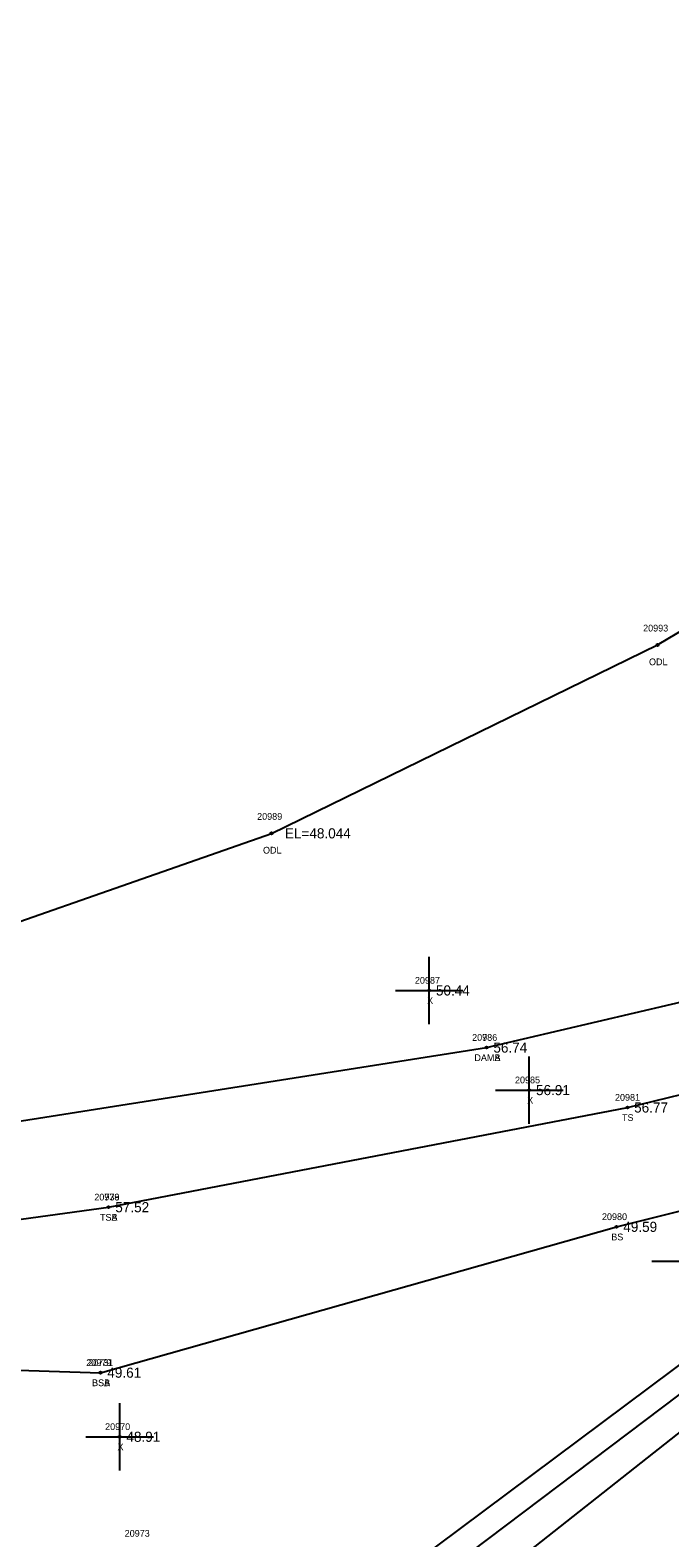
# Model space of a CAD drawing. Extents: x 2420351 to 2422725, y 845330 to 846558.
# Drawn here: x 2421942.5 to 2422037.3, y 845997.2 to 846220.7 of the extents above; entities that cross this region are included whole.
import ezdxf

# ---------------------------------------------------------------- set-up
doc = ezdxf.new("R2010")
doc.units = 0
for name, color, linetype in [('RD_DTM_BkLn2', 7, 'Continuous'), ('RD_DTM_BkLn_txCode', 7, 'Continuous'), ('RD_EX_Dam', 7, 'Continuous'), ('RD_EX_Dam_txCode', 7, 'Continuous'), ('RD_EX_H2O', 7, 'Continuous'), ('RD_EX_H2O_txCode', 7, 'Continuous'), ('RD_EX_Misc', 7, 'Continuous'), ('RD_EX_Misc_txCode', 7, 'Continuous'), ('RD_EX_Road', 7, 'Continuous'), ('RD_EX_TX_Dam_ELEV', 7, 'Continuous'), ('RD_EX_TX_H2O_ELEV', 7, 'Continuous'), ('RD_EX_TX_Misc_ELEV', 7, 'Continuous'), ('RD_SMD_Locator', 7, 'Continuous')]:
    doc.layers.add(name, color=color, linetype=linetype)

msp = doc.modelspace()

# ---------------------------------------------------------------- linework, layer by layer
at = {"layer": 'RD_DTM_BkLn2'}
for points in [[(2421703.45, 845999.67), (2421800.66, 846017.53), (2421880.42, 846035.1), (2421923.1, 846041.94), (2421954.1, 846046.17), (2421954.1, 846046.17), (2422030.99, 846060.95), (2422065.43, 846069.36), (2422120.97, 846103.75), (2422145.48, 846129.05), (2422185.42, 846182.09)], [(2421867.66, 845896.73), (2421878.61, 845908.51), (2421930.41, 845948.62), (2421974.68, 845974.99), (2422048.32, 846029.98), (2422081.44, 846056.32)], [(2421952.92, 846021.64), (2422029.38, 846043.26), (2422081.44, 846056.32)], [(2421867.66, 845896.73), (2421933.04, 845943.88), (2421976.81, 845971.64), (2422049.15, 846026.28), (2422084.34, 846055.89)], [(2421705.85, 845990.03), (2421805.22, 846005.36), (2421884.52, 846023.82), (2421952.92, 846021.64)]]:
    msp.add_lwpolyline(points, dxfattribs=at)
at = {"layer": 'RD_EX_Dam'}
msp.add_lwpolyline([(2421703.45, 845999.67), (2421702.66, 846017.28), (2421795.13, 846032.49), (2421876.44, 846046.05), (2421920.78, 846055.77), (2422010.13, 846069.83), (2422010.13, 846069.83), (2422059.48, 846081.4), (2422106.12, 846132.59), (2422121.56, 846164.68), (2422122.27, 846182.92)], dxfattribs=at)
at = {"layer": 'RD_EX_H2O'}
msp.add_lwpolyline([(2421916.6, 846080.01), (2421978.24, 846101.59), (2422035.44, 846129.51), (2422086.04, 846159.54), (2422093.43, 846179.83)], dxfattribs=at)
at = {"layer": 'RD_EX_Misc'}
for p, q in [((2422001.62, 846073.3), (2422001.62, 846083.3)), ((2421996.62, 846078.3), (2422006.62, 846078.3)), ((2422016.45, 846058.53), (2422016.45, 846068.53)), ((2422011.45, 846063.53), (2422021.45, 846063.53)), ((2422034.63, 846038.17), (2422044.63, 846038.17)), ((2421955.75, 846007.14), (2421955.75, 846017.14)), ((2421950.75, 846012.14), (2421960.75, 846012.14))]:
    msp.add_line(p, q, dxfattribs=at)
at = {"layer": 'RD_EX_Road'}
msp.add_lwpolyline([(2421810.77, 845819.82), (2421809.69, 845832.82), (2421803.88, 845842.86), (2421852.96, 845873.69), (2421939.48, 845935.12), (2421980.78, 845967.01), (2422140.12, 846092.81), (2422210.03, 846148.43), (2422282.88, 846205.21), (2422291.79, 846212.09), (2422354.49, 846261.98), (2422400.82, 846297.88), (2422417.34, 846311.65), (2422435.4, 846324.77), (2422462.49, 846346.77), (2422472.85, 846354.85), (2422502.3, 846378.16), (2422578.05, 846437.54), (2422605.64, 846459.09), (2422626.64, 846476.17), (2422642.61, 846488.86)], dxfattribs=at)
at = {"layer": 'RD_SMD_Locator'}
for centre in [(2422035.44, 846129.51), (2421978.24, 846101.59), (2422001.62, 846078.3), (2422010.13, 846069.83), (2422010.13, 846069.83), (2422016.45, 846063.53), (2422030.99, 846060.95), (2421954.1, 846046.17), (2421954.1, 846046.17), (2422029.38, 846043.26), (2421952.92, 846021.64), (2421952.92, 846021.64), (2421955.75, 846012.14)]:
    msp.add_circle(centre, 0.15, dxfattribs=at)

# ---------------------------------------------------------------- texts
at = {"layer": 'RD_DTM_BkLn_txCode'}
for s, p in [('20981', (2422029.15, 846061.95)), ('TS', (2422030.19, 846058.95)), ('20739', (2421951.99, 846047.17)), ('20978', (2421951.99, 846047.17)), ('TSA', (2421952.82, 846044.17)), ('TSB', (2421952.84, 846044.17)), ('20980', (2422027.22, 846044.26)), ('BS', (2422028.6, 846041.26)), ('20979', (2421950.8, 846022.64)), ('20731', (2421951.08, 846022.64)), ('BSA', (2421951.65, 846019.64)), ('BSB', (2421951.67, 846019.64))]:
    msp.add_text(s, height=1, dxfattribs=at).set_placement(p)
at = {"layer": 'RD_EX_Dam_txCode'}
for s, p in [('20736', (2422007.98, 846070.83)), ('20986', (2422007.98, 846070.83)), ('DAMA', (2422008.31, 846067.83)), ('DAMB', (2422008.32, 846067.83))]:
    msp.add_text(s, height=1, dxfattribs=at).set_placement(p)
at = {"layer": 'RD_EX_H2O_txCode'}
for s, p in [('20993', (2422033.32, 846131.51)), ('ODL', (2422034.19, 846126.51)), ('20989', (2421976.12, 846103.59)), ('ODL', (2421976.99, 846098.59)), ('20973', (2421956.49, 845997.32))]:
    msp.add_text(s, height=1, dxfattribs=at).set_placement(p)
at = {"layer": 'RD_EX_Misc_txCode'}
for s, p in [('20987', (2421999.5, 846079.3)), ('X', (2422001.31, 846076.3)), ('20985', (2422014.33, 846064.53)), ('X', (2422016.14, 846061.53)), ('20970', (2421953.59, 846013.14)), ('X', (2421955.43, 846010.14))]:
    msp.add_text(s, height=1, dxfattribs=at).set_placement(p)
at = {"layer": 'RD_EX_TX_Dam_ELEV'}
msp.add_text('56.74', height=1.5, dxfattribs=at).set_placement((2422011.13, 846069.08))
msp.add_text('56.74', height=1.5, dxfattribs=at).set_placement((2422011.13, 846069.08))
at = {"layer": 'RD_EX_TX_H2O_ELEV'}
msp.add_text('EL=48.044', height=1.5, dxfattribs=at).set_placement((2421980.24, 846100.84))
at = {"layer": 'RD_EX_TX_Misc_ELEV'}
for s, p in [('50.44', (2422002.62, 846077.55)), ('56.91', (2422017.45, 846062.78)), ('56.77', (2422031.99, 846060.2)), ('57.52', (2421955.1, 846045.42)), ('57.52', (2421955.1, 846045.42)), ('49.59', (2422030.38, 846042.51)), ('49.61', (2421953.92, 846020.89)), ('49.61', (2421953.92, 846020.89)), ('48.91', (2421956.75, 846011.39))]:
    msp.add_text(s, height=1.5, dxfattribs=at).set_placement(p)

doc.saveas('drawing.dxf')
